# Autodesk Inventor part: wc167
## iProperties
Shininess: 64.0
Length Units: 11272
Angle Units: 11279
Time Units: 11290
Mass Units: 11286
Length Display Precision: 3
Angle Display Precision: 2
Compacted: True
Part Number: wc167
Document SubType Name: Modeling
Created: 2004-08
Designer: John Blackburn
Manufacturer: Standard
Standards Organization: Custom
Material: Phenolic
Density: 0.0
Volumn: 0.0
Area: 0.0
PropertySet Name: Model Information
Control State: 0
Master: False
Checked Out: False
Author: John Blackburn
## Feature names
1. Base1
